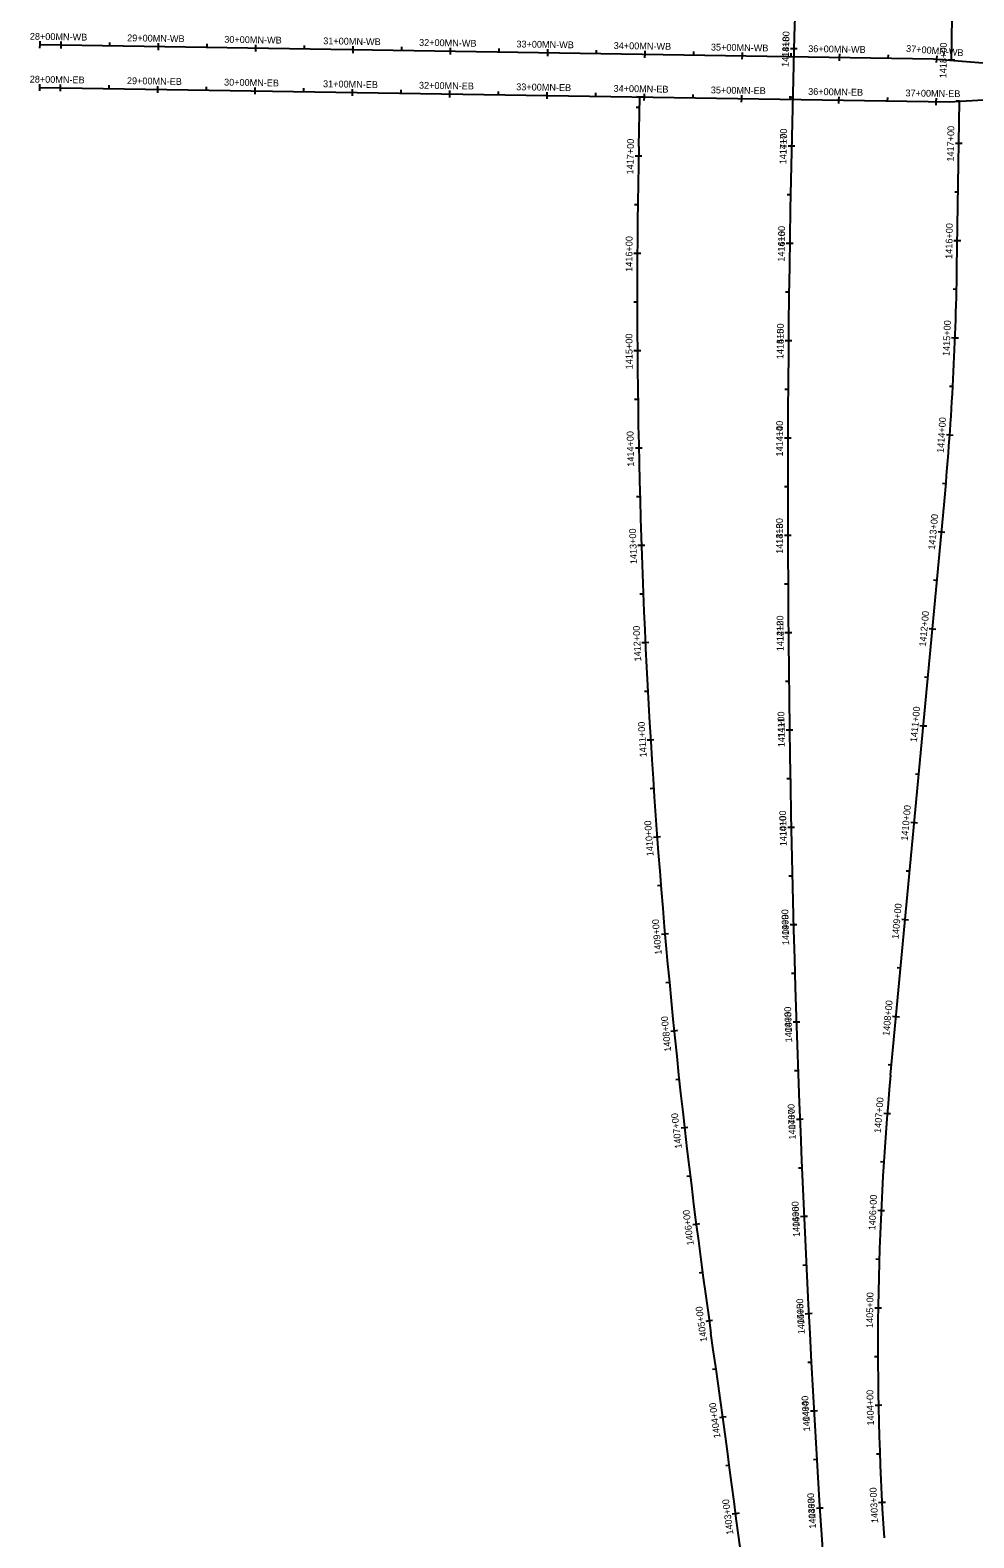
# Model space of a CAD drawing. Extents: x 596007 to 607538, y 326212 to 405053.
# Drawn here: x 602032 to 603002, y 364628 to 366177 of the extents above; entities that cross this region are included whole.
import ezdxf

# ---------------------------------------------------------------- set-up
doc = ezdxf.new("R2010")
doc.units = 0
doc.layers.add('P_ALI_200', color=7, linetype='Continuous')
doc.layers.add('P_ALI_200_Sta', color=7, linetype='Continuous')

msp = doc.modelspace()

# ---------------------------------------------------------------- linework, layer by layer
at = {"layer": 'P_ALI_200'}
for points in [[(602979.1, 366146.3), (602984.7, 366498.9)], [(602042.4, 366162.4), (602960.4, 366147.8)], [(602960.4, 366147.8), (603237.6, 366125.7)], [(602042.3, 366118.4), (602976.8, 366103.5)], [(602976.8, 366103.5), (603270.2, 366120.7)], [(602657.7, 366057.7), (602658.7, 366108.6)], [(602984.7, 365933), (602987.4, 366104.2)], [(602916.5, 365103.7), (602971.4, 365689.5)]]:
    msp.add_lwpolyline(points, dxfattribs=at)
for centre, radius, start, end in [((619326.8, 365700.7), 16516, 171.89148, 185.04999), ((619326.8, 365700.7), 16516, 171.89148, 185.04999), ((610156.1, 365902.1), 7500, 178.81127, 188.15156), ((599840.1, 365982.9), 3145, 354.6473, 359.0919), ((605903.4, 364823.9), 3000, 174.6473, 183.7373), ((586893.5, 362570), 16000, 6.14964, 8.15156)]:
    msp.add_arc(centre, radius, start, end, dxfattribs=at)
at = {"layer": 'P_ALI_200_Sta'}
for points in [[(602042.3, 366158.9), (602042.4, 366162.4)], [(602042.4, 366162.4), (602042.5, 366165.9)], [(602042.4, 366162.4), (602042.4, 366162.4)], [(602064.2, 366162), (602064.3, 366165.5)], [(602064.2, 366162), (602064.2, 366162)], [(602064.2, 366158.5), (602064.2, 366162)], [(602114.2, 366161.2), (602114.3, 366164.7)], [(602164.2, 366160.4), (602164.3, 366163.9)], [(602164.2, 366160.4), (602164.2, 366160.4)], [(602164.2, 366156.9), (602164.2, 366160.4)], [(602214.2, 366159.6), (602214.3, 366163.1)], [(602264.2, 366158.8), (602264.3, 366162.3)], [(602264.2, 366158.8), (602264.2, 366158.8)], [(602264.2, 366155.3), (602264.2, 366158.8)], [(602314.2, 366158.1), (602314.3, 366161.6)], [(602364.2, 366157.3), (602364.3, 366160.8)], [(602364.2, 366157.3), (602364.2, 366157.3)], [(602364.2, 366153.8), (602364.2, 366157.3)], [(602414.2, 366156.5), (602414.3, 366160)], [(602464.2, 366155.7), (602464.3, 366159.2)], [(602514.2, 366154.9), (602514.2, 366158.4)], [(602564.2, 366154.1), (602564.2, 366157.6)], [(602614.2, 366153.3), (602614.2, 366156.8)], [(602817.1, 366158.1), (602813.6, 366158.2)], [(602817.1, 366158.1), (602813.6, 366158.2)], [(602817.1, 366158.1), (602817.1, 366158.1)], [(602820.6, 366158), (602817.1, 366158.1)], [(602817.1, 366158.1), (602817.1, 366158.1)], [(602820.6, 366158), (602817.1, 366158.1)], [(602464.1, 366152.2), (602464.2, 366155.7)], [(602464.2, 366155.7), (602464.2, 366155.7)], [(602564.1, 366150.6), (602564.2, 366154.1)], [(602564.2, 366154.1), (602564.2, 366154.1)], [(602664.1, 366149), (602664.2, 366152.5)], [(602664.2, 366152.5), (602664.2, 366156)], [(602664.2, 366152.5), (602664.2, 366152.5)], [(602714.2, 366151.7), (602714.2, 366155.2)], [(602764.1, 366147.4), (602764.2, 366150.9)], [(602764.2, 366150.9), (602764.2, 366154.4)], [(602764.2, 366150.9), (602764.2, 366150.9)], [(602814.2, 366150.1), (602814.2, 366153.6)], [(602864.1, 366149.3), (602864.2, 366152.8)], [(602864.1, 366149.3), (602864.1, 366149.3)], [(602864.1, 366145.8), (602864.1, 366149.3)], [(602914.1, 366148.5), (602914.2, 366152)], [(602963.8, 366144), (602964.1, 366147.5)], [(602964.1, 366147.5), (602964.4, 366151)], [(602964.1, 366147.5), (602964.1, 366147.5)], [(602979.1, 366146.5), (602975.6, 366146.6)], [(602979.1, 366146.3), (602975.6, 366146.4)], [(602979.1, 366146.5), (602979.1, 366146.5)], [(602982.6, 366146.5), (602979.1, 366146.5)], [(602979.1, 366146.3), (602979.1, 366146.3)], [(602982.6, 366146.3), (602979.1, 366146.3)], [(602042.2, 366114.9), (602042.3, 366118.4)], [(602042.3, 366118.4), (602042.3, 366121.9)], [(602042.3, 366118.4), (602042.3, 366118.4)], [(602063.5, 366118), (602063.6, 366121.5)], [(602063.5, 366118), (602063.5, 366118)], [(602063.5, 366114.5), (602063.5, 366118)], [(602113.5, 366117.2), (602113.6, 366120.7)], [(602163.5, 366116.4), (602163.6, 366119.9)], [(602163.5, 366116.4), (602163.5, 366116.4)], [(602163.5, 366112.9), (602163.5, 366116.4)], [(602213.5, 366115.6), (602213.6, 366119.1)], [(602263.5, 366114.9), (602263.6, 366118.4)], [(602263.5, 366114.9), (602263.5, 366114.9)], [(602263.5, 366111.4), (602263.5, 366114.9)], [(602313.5, 366114.1), (602313.6, 366117.6)], [(602363.5, 366113.3), (602363.6, 366116.8)], [(602363.5, 366113.3), (602363.5, 366113.3)], [(602363.5, 366109.8), (602363.5, 366113.3)], [(602413.5, 366112.5), (602413.6, 366116)], [(602463.4, 366108.2), (602463.5, 366111.7)], [(602463.5, 366111.7), (602463.6, 366115.2)], [(602463.5, 366111.7), (602463.5, 366111.7)], [(602513.5, 366110.9), (602513.5, 366114.4)], [(602563.4, 366106.6), (602563.5, 366110.1)], [(602563.5, 366110.1), (602563.5, 366113.6)], [(602563.5, 366110.1), (602563.5, 366110.1)], [(602613.5, 366109.3), (602613.5, 366112.8)], [(602663.5, 366108.5), (602663.5, 366112)], [(602713.5, 366107.7), (602713.5, 366111.2)], [(602763.5, 366106.9), (602763.5, 366110.4)], [(602658.5, 366097.7), (602655, 366097.8)], [(602658.7, 366108.6), (602655.2, 366108.7)], [(602658.7, 366108.6), (602658.7, 366108.6)], [(602662.2, 366108.5), (602658.7, 366108.6)], [(602663.4, 366105), (602663.5, 366108.5)], [(602663.5, 366108.5), (602663.5, 366108.5)], [(602763.4, 366103.4), (602763.5, 366106.9)], [(602763.5, 366106.9), (602763.5, 366106.9)], [(602815.8, 366108.1), (602812.3, 366108.2)], [(602815.8, 366108.1), (602812.3, 366108.2)], [(602813.5, 366106.1), (602813.5, 366109.6)], [(602863.4, 366105.3), (602863.5, 366108.8)], [(602863.4, 366105.3), (602863.4, 366105.3)], [(602863.4, 366101.8), (602863.4, 366105.3)], [(602913.4, 366104.5), (602913.5, 366108)], [(602963.4, 366103.8), (602963.5, 366107.3)], [(602963.4, 366103.8), (602963.4, 366103.8)], [(602963.4, 366100.3), (602963.4, 366103.8)], [(602987.4, 366104.2), (602983.9, 366104.2)], [(602987.4, 366104.2), (602987.4, 366104.2)], [(602990.9, 366104.1), (602987.4, 366104.2)], [(602814.7, 366058.1), (602811.2, 366058.2)], [(602814.7, 366058.1), (602811.2, 366058.2)], [(602814.7, 366058.1), (602814.7, 366058.1)], [(602818.2, 366058), (602814.7, 366058.1)], [(602814.7, 366058.1), (602814.7, 366058.1)], [(602818.2, 366058), (602814.7, 366058.1)], [(602986.7, 366061), (602983.2, 366061)], [(602986.7, 366061), (602986.7, 366061)], [(602990.2, 366060.9), (602986.7, 366061)], [(602657.5, 366047.8), (602654, 366047.8)], [(602657.5, 366047.8), (602657.5, 366047.8)], [(602661, 366047.7), (602657.5, 366047.8)], [(602813.7, 366008.1), (602810.2, 366008.2)], [(602813.7, 366008.1), (602810.2, 366008.2)], [(602985.9, 366011), (602982.4, 366011)], [(602656.7, 365997.8), (602653.2, 365997.8)], [(602812.8, 365958.1), (602809.3, 365958.2)], [(602812.8, 365958.1), (602809.3, 365958.2)], [(602812.8, 365958.1), (602812.8, 365958.1)], [(602816.3, 365958.1), (602812.8, 365958.1)], [(602812.8, 365958.1), (602812.8, 365958.1)], [(602816.3, 365958.1), (602812.8, 365958.1)], [(602985.1, 365961), (602981.6, 365961)], [(602985.1, 365961), (602985.1, 365961)], [(602988.6, 365960.9), (602985.1, 365961)], [(602656.2, 365947.8), (602652.7, 365947.8)], [(602656.2, 365947.8), (602656.2, 365947.8)], [(602659.7, 365947.7), (602656.2, 365947.8)], [(602984.3, 365911), (602980.8, 365911.1)], [(602656.1, 365897.8), (602652.6, 365897.8)], [(602812.1, 365908.1), (602808.6, 365908.2)], [(602812.1, 365908.1), (602808.6, 365908.2)], [(602656.3, 365847.8), (602652.8, 365847.7)], [(602656.3, 365847.8), (602656.3, 365847.8)], [(602659.8, 365847.8), (602656.3, 365847.8)], [(602811.6, 365858.1), (602808.1, 365858.2)], [(602811.6, 365858.1), (602808.1, 365858.2)], [(602811.6, 365858.1), (602811.6, 365858.1)], [(602815.1, 365858.1), (602811.6, 365858.1)], [(602811.6, 365858.1), (602811.6, 365858.1)], [(602815.1, 365858.1), (602811.6, 365858.1)], [(602982.7, 365861), (602979.2, 365861.2)], [(602982.7, 365861), (602982.7, 365861)], [(602986.2, 365860.9), (602982.7, 365861)], [(602811.2, 365808.1), (602807.7, 365808.1)], [(602811.2, 365808.1), (602807.7, 365808.1)], [(602980.4, 365811.1), (602976.9, 365811.3)], [(602656.8, 365797.8), (602653.3, 365797.7)], [(602810.9, 365758.1), (602807.4, 365758.1)], [(602810.9, 365758.1), (602807.4, 365758.1)], [(602810.9, 365758.1), (602810.9, 365758.1)], [(602814.4, 365758.1), (602810.9, 365758.1)], [(602810.9, 365758.1), (602810.9, 365758.1)], [(602814.4, 365758.1), (602810.9, 365758.1)], [(602977.3, 365761.2), (602973.8, 365761.4)], [(602977.3, 365761.2), (602977.3, 365761.2)], [(602980.8, 365760.9), (602977.3, 365761.2)], [(602657.7, 365747.8), (602654.2, 365747.7)], [(602657.7, 365747.8), (602657.7, 365747.8)], [(602661.2, 365747.8), (602657.7, 365747.8)], [(602810.8, 365708.1), (602807.3, 365708.1)], [(602810.8, 365708.1), (602807.3, 365708.1)], [(602973.4, 365711.3), (602969.9, 365711.6)], [(602658.8, 365697.8), (602655.3, 365697.7)], [(602968.8, 365661.5), (602965.3, 365661.9)], [(602968.8, 365661.5), (602968.8, 365661.5)], [(602972.2, 365661.2), (602968.8, 365661.5)], [(602660.4, 365647.8), (602656.9, 365647.7)], [(602663.9, 365647.9), (602660.4, 365647.8)], [(602660.4, 365647.8), (602660.4, 365647.8)], [(602810.9, 365658.1), (602807.4, 365658.1)], [(602810.9, 365658.1), (602807.4, 365658.1)], [(602810.9, 365658.1), (602810.9, 365658.1)], [(602814.4, 365658.1), (602810.9, 365658.1)], [(602810.9, 365658.1), (602810.9, 365658.1)], [(602814.4, 365658.1), (602810.9, 365658.1)], [(602811.1, 365608.1), (602807.6, 365608.1)], [(602811.1, 365608.1), (602807.6, 365608.1)], [(602964.1, 365611.8), (602960.6, 365612.1)], [(602662.2, 365597.8), (602658.7, 365597.7)], [(602811.4, 365558.1), (602807.9, 365558.1)], [(602811.4, 365558.1), (602807.9, 365558.1)], [(602814.9, 365558.2), (602811.4, 365558.1)], [(602814.9, 365558.2), (602811.4, 365558.1)], [(602811.4, 365558.1), (602811.4, 365558.1)], [(602811.4, 365558.1), (602811.4, 365558.1)], [(602959.4, 365562), (602956, 365562.3)], [(602959.4, 365562), (602959.4, 365562)], [(602962.9, 365561.7), (602959.4, 365562)], [(602664.4, 365547.9), (602660.9, 365547.7)], [(602667.9, 365548.1), (602664.4, 365547.9)], [(602664.4, 365547.9), (602664.4, 365547.9)], [(602811.9, 365508.1), (602808.4, 365508.1)], [(602811.9, 365508.1), (602808.4, 365508.1)], [(602954.8, 365512.2), (602951.3, 365512.5)], [(602667, 365498), (602663.5, 365497.8)], [(602950.1, 365462.4), (602946.6, 365462.7)], [(602950.1, 365462.4), (602950.1, 365462.4)], [(602953.6, 365462.1), (602950.1, 365462.4)], [(602669.8, 365448), (602666.3, 365447.8)], [(602673.3, 365448.2), (602669.8, 365448)], [(602669.8, 365448), (602669.8, 365448)], [(602812.6, 365458.1), (602809.1, 365458.1)], [(602812.6, 365458.1), (602809.1, 365458.1)], [(602816.1, 365458.2), (602812.6, 365458.1)], [(602816.1, 365458.2), (602812.6, 365458.1)], [(602812.6, 365458.1), (602812.6, 365458.1)], [(602812.6, 365458.1), (602812.6, 365458.1)], [(602945.4, 365412.6), (602942, 365413)], [(602673, 365398.1), (602669.5, 365397.9)], [(602813.4, 365408.1), (602809.9, 365408.1)], [(602813.4, 365408.1), (602809.9, 365408.1)], [(602814.4, 365358.1), (602810.9, 365358.1)], [(602814.4, 365358.1), (602810.9, 365358.1)], [(602817.9, 365358.2), (602814.4, 365358.1)], [(602817.9, 365358.2), (602814.4, 365358.1)], [(602814.4, 365358.1), (602814.4, 365358.1)], [(602814.4, 365358.1), (602814.4, 365358.1)], [(602940.8, 365362.9), (602937.3, 365363.2)], [(602940.8, 365362.9), (602940.8, 365362.9)], [(602944.3, 365362.5), (602940.8, 365362.9)], [(602676.5, 365348.3), (602673, 365348)], [(602680, 365348.5), (602676.5, 365348.3)], [(602676.5, 365348.3), (602676.5, 365348.3)], [(602815.5, 365308.2), (602812, 365308.1)], [(602815.5, 365308.2), (602812, 365308.1)], [(602936.1, 365313.1), (602932.6, 365313.4)], [(602680.4, 365298.4), (602676.9, 365298.1)], [(602816.7, 365258.2), (602813.2, 365258.1)], [(602816.7, 365258.2), (602813.2, 365258.1)], [(602820.2, 365258.3), (602816.7, 365258.2)], [(602820.2, 365258.3), (602816.7, 365258.2)], [(602816.7, 365258.2), (602816.7, 365258.2)], [(602816.7, 365258.2), (602816.7, 365258.2)], [(602931.4, 365263.3), (602928, 365263.6)], [(602931.4, 365263.3), (602931.4, 365263.3)], [(602934.9, 365263), (602931.4, 365263.3)], [(602684.6, 365248.6), (602681.1, 365248.3)], [(602688.1, 365248.9), (602684.6, 365248.6)], [(602684.6, 365248.6), (602684.6, 365248.6)], [(602926.8, 365213.5), (602923.3, 365213.8)], [(602689.1, 365198.8), (602685.6, 365198.5)], [(602818.2, 365208.2), (602814.7, 365208.1)], [(602818.2, 365208.2), (602814.7, 365208.1)], [(602819.7, 365158.2), (602816.2, 365158.1)], [(602819.7, 365158.2), (602816.2, 365158.1)], [(602823.2, 365158.3), (602819.7, 365158.2)], [(602823.2, 365158.3), (602819.7, 365158.2)], [(602819.7, 365158.2), (602819.7, 365158.2)], [(602819.7, 365158.2), (602819.7, 365158.2)], [(602922.1, 365163.7), (602918.6, 365164.1)], [(602922.1, 365163.7), (602922.1, 365163.7)], [(602925.6, 365163.4), (602922.1, 365163.7)], [(602694, 365149), (602690.5, 365148.7)], [(602697.4, 365149.4), (602694, 365149)], [(602694, 365149), (602694, 365149)], [(602821.4, 365108.3), (602817.9, 365108.1)], [(602821.4, 365108.3), (602817.9, 365108.1)], [(602917.5, 365113.9), (602914, 365114.3)], [(602699.2, 365099.3), (602695.7, 365098.9)], [(602823.3, 365058.3), (602819.8, 365058.1)], [(602823.3, 365058.3), (602819.8, 365058.1)], [(602826.8, 365058.4), (602823.3, 365058.3)], [(602826.8, 365058.4), (602823.3, 365058.3)], [(602823.3, 365058.3), (602823.3, 365058.3)], [(602823.3, 365058.3), (602823.3, 365058.3)], [(602913.1, 365064.1), (602909.6, 365064.4)], [(602913.1, 365064.1), (602913.1, 365064.1)], [(602916.5, 365063.9), (602913.1, 365064.1)], [(602704.7, 365049.6), (602701.2, 365049.2)], [(602708.1, 365050), (602704.7, 365049.6)], [(602704.7, 365049.6), (602704.7, 365049.6)], [(602909.5, 365014.3), (602906, 365014.5)], [(602710.5, 365000), (602707, 364999.5)], [(602825.3, 365008.3), (602821.8, 365008.2)], [(602825.3, 365008.3), (602821.8, 365008.2)], [(602906.7, 364964.3), (602903.2, 364964.5)], [(602906.7, 364964.3), (602906.7, 364964.3)], [(602910.2, 364964.2), (602906.7, 364964.3)], [(602716.7, 364950.3), (602713.2, 364949.9)], [(602720.2, 364950.8), (602716.7, 364950.3)], [(602716.7, 364950.3), (602716.7, 364950.3)], [(602827.5, 364958.4), (602824, 364958.2)], [(602827.5, 364958.4), (602824, 364958.2)], [(602831, 364958.5), (602827.5, 364958.4)], [(602831, 364958.5), (602827.5, 364958.4)], [(602827.5, 364958.4), (602827.5, 364958.4)], [(602827.5, 364958.4), (602827.5, 364958.4)], [(602829.8, 364908.4), (602826.3, 364908.3)], [(602829.8, 364908.4), (602826.3, 364908.3)], [(602904.8, 364914.4), (602901.3, 364914.5)], [(602723.2, 364900.8), (602719.7, 364900.3)], [(602832.3, 364858.5), (602828.8, 364858.3)], [(602832.3, 364858.5), (602828.8, 364858.3)], [(602835.8, 364858.7), (602832.3, 364858.5)], [(602835.8, 364858.7), (602832.3, 364858.5)], [(602832.3, 364858.5), (602832.3, 364858.5)], [(602832.3, 364858.5), (602832.3, 364858.5)], [(602903.7, 364864.4), (602900.2, 364864.4)], [(602903.7, 364864.4), (602903.7, 364864.4)], [(602907.2, 364864.3), (602903.7, 364864.4)], [(602730.1, 364851.2), (602726.6, 364850.7)], [(602733.5, 364851.7), (602730.1, 364851.2)], [(602730.1, 364851.2), (602730.1, 364851.2)], [(602903.4, 364814.4), (602899.9, 364814.4)], [(602737.1, 364801.7), (602733.6, 364801.2)], [(602834.9, 364808.6), (602831.4, 364808.4)], [(602834.9, 364808.6), (602831.4, 364808.4)], [(602904, 364764.4), (602900.5, 364764.3)], [(602907.5, 364764.5), (602904, 364764.4)], [(602904, 364764.4), (602904, 364764.4)], [(602744, 364752.2), (602740.5, 364751.7)], [(602747.5, 364752.7), (602744, 364752.2)], [(602744, 364752.2), (602744, 364752.2)], [(602837.7, 364758.6), (602834.2, 364758.4)], [(602837.7, 364758.6), (602834.2, 364758.4)], [(602841.2, 364758.8), (602837.7, 364758.6)], [(602841.2, 364758.8), (602837.7, 364758.6)], [(602837.7, 364758.6), (602837.7, 364758.6)], [(602837.7, 364758.6), (602837.7, 364758.6)], [(602750.7, 364702.7), (602747.3, 364702.2)], [(602840.6, 364708.7), (602837.1, 364708.5)], [(602840.6, 364708.7), (602837.1, 364708.5)], [(602905.4, 364714.4), (602901.9, 364714.3)], [(602843.7, 364658.8), (602840.2, 364658.6)], [(602843.7, 364658.8), (602840.2, 364658.6)], [(602847.2, 364659), (602843.7, 364658.8)], [(602847.2, 364659), (602843.7, 364658.8)], [(602843.7, 364658.8), (602843.7, 364658.8)], [(602843.7, 364658.8), (602843.7, 364658.8)], [(602907.7, 364664.5), (602904.2, 364664.3)], [(602911.2, 364664.7), (602907.7, 364664.5)], [(602907.7, 364664.5), (602907.7, 364664.5)], [(602757.3, 364653.1), (602753.8, 364652.6)], [(602760.8, 364653.6), (602757.3, 364653.1)], [(602757.3, 364653.1), (602757.3, 364653.1)]]:
    msp.add_lwpolyline(points, dxfattribs=at)

# ---------------------------------------------------------------- texts
for s, height, rotation, p in [('28+00MN-WB', 7, 359.0919, (602031.9, 366167.5)), ('29+00MN-WB', 7, 359.0919, (602131.9, 366165.9)), ('1418+00', 7, 88.4132, (602811.6, 366139.4)), ('27+78MN-WB', 0.0000000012, 359.0919, (602042.5, 366167.4)), ('30+00MN-WB', 7, 359.0919, (602231.7, 366164.4)), ('31+00MN-WB', 7, 359.0919, (602333.4, 366162.8)), ('32+00MN-WB', 7, 359.0919, (602431.9, 366161.2)), ('33+00MN-WB', 7, 359.0919, (602531.9, 366159.6)), ('34+00MN-WB', 7, 359.0919, (602631.9, 366158)), ('35+00MN-WB', 7, 359.0919, (602731.8, 366156.4)), ('1418', 7, 88.4132, (602811.9, 366149.6)), ('36+00MN-WB', 7, 359.0919, (602831.8, 366154.8)), ('37+00MN-WB', 7, 355.4384, (602932.2, 366155.1)), ('1418+00', 7, 89.0919, (602973.8, 366127.8)), ('1418+00', 0.0000000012, 89.0919, (602974.1, 366146.4)), ('28+00MN-EB', 7, 359.0919, (602031.8, 366123.5)), ('29+00MN-EB', 7, 359.0919, (602131.7, 366121.9)), ('30+00MN-EB', 7, 359.0919, (602231.5, 366120.4)), ('31+00MN-EB', 7, 359.0919, (602333.2, 366118.7)), ('27+79MN-EB', 0.0000000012, 359.0919, (602042.4, 366123.4)), ('32+00MN-EB', 7, 359.0919, (602431.8, 366117.2)), ('33+00MN-EB', 7, 359.0919, (602531.7, 366115.6)), ('34+00MN-EB', 7, 359.0919, (602631.7, 366114)), ('35+00MN-EB', 7, 359.0919, (602731.7, 366112.4)), ('36+00MN-EB', 7, 359.0919, (602831.7, 366110.8)), ('37+00MN-EB', 7, 359.0919, (602931.7, 366109.3)), ('1417+61', 0.0000000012, 88.8113, (602653.7, 366108.7)), ('1417+43', 0.0000000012, 89.0919, (602982.4, 366104.2)), ('1417+00', 7, 88.8872, (602652.1, 366029)), ('1417+00', 7, 88.7601, (602809.3, 366039.4)), ('1417', 7, 88.7601, (602809.5, 366049.6)), ('1417+00', 7, 89.0919, (602981.4, 366042.2)), ('1416+00', 7, 89.107, (602807.5, 365939.4)), ('1416+00', 7, 89.0919, (602979.8, 365942.3)), ('1416+00', 7, 89.6512, (602651.1, 365929)), ('1416', 7, 89.107, (602807.7, 365949.6)), ('1415+00', 7, 87.7795, (602977, 365842.4)), ('1415+00', 7, 90.4151, (602651.4, 365828.9)), ('1415+00', 7, 89.4539, (602806.4, 365839.3)), ('1415', 7, 89.4539, (602806.5, 365849.6)), ('1414+00', 7, 89.8008, (602805.8, 365739.3)), ('1414', 7, 89.8008, (602805.9, 365749.6)), ('1414+00', 7, 85.9577, (602971, 365742.8)), ('1414+00', 7, 91.1791, (602653, 365728.8)), ('1413+00', 7, 84.6473, (602962, 365643.3)), ('1413+00', 7, 91.943, (602656, 365628.8)), ('1413+00', 7, 90.1477, (602805.9, 365639.3)), ('1413', 7, 90.1477, (602805.9, 365649.5)), ('1412+00', 7, 90.4946, (602806.6, 365539.3)), ('1412', 7, 90.4946, (602806.5, 365549.5)), ('1412+00', 7, 84.6473, (602952.7, 365543.7)), ('1412+00', 7, 92.707, (602660.3, 365528.9)), ('1411+00', 7, 90.8415, (602807.8, 365440.7)), ('1411+00', 7, 84.6473, (602943.5, 365445.6)), ('1411+00', 7, 93.4709, (602665.9, 365430.4)), ('1411', 7, 90.8415, (602807.7, 365450.4)), ('1410+00', 7, 91.1884, (602809.8, 365339)), ('1410', 7, 91.1884, (602809.6, 365349.2)), ('1410+00', 7, 84.6473, (602934, 365344.3)), ('1410+00', 7, 94.2348, (602673, 365328.9)), ('1409+00', 7, 91.5354, (602812.3, 365237.5)), ('1409+00', 7, 84.6473, (602924.6, 365243.3)), ('1409+00', 7, 94.9988, (602681.4, 365227.7)), ('1409', 7, 91.5354, (602812, 365247.8)), ('1408+00', 7, 91.8823, (602815.4, 365137.5)), ('1408', 7, 91.8823, (602815.1, 365147.8)), ('1408+00', 7, 84.6473, (602915.2, 365143.8)), ('1408+00', 7, 95.7627, (602691.1, 365128.1)), ('1407+00', 7, 92.2292, (602819.1, 365037.6)), ('1407+00', 7, 85.4066, (602906.4, 365044.1)), ('1407+00', 7, 96.5267, (602702, 365028.6)), ('1407', 7, 92.2292, (602818.7, 365047.8)), ('1406+00', 7, 87.3165, (602900.8, 364944.1)), ('1406+00', 7, 97.2906, (602714.3, 364929.3)), ('1406+00', 7, 92.5761, (602823.4, 364937.6)), ('1406', 7, 92.5761, (602823, 364947.9)), ('1405+00', 7, 92.923, (602828.4, 364837.7)), ('1405+00', 7, 89.2263, (602898.4, 364843.9)), ('1405+00', 7, 98.0546, (602728, 364830.2)), ('1405', 7, 92.923, (602827.8, 364848)), ('1404+00', 7, 91.1362, (602899.4, 364743.8)), ('1404+00', 7, 97.8389, (602741.8, 364731.2)), ('1404+00', 7, 93.2699, (602833.9, 364737.9)), ('1404', 7, 93.2699, (602833.3, 364748.1)), ('1403+00', 7, 93.6168, (602840, 364638)), ('1403+00', 7, 93.046, (602903.8, 364643.7)), ('1403+00', 7, 97.4808, (602755, 364632.1)), ('1403', 7, 93.6168, (602839.4, 364648.3))]:
    msp.add_text(s, height=height, rotation=rotation, dxfattribs=at).set_placement(p)

doc.saveas('drawing.dxf')
